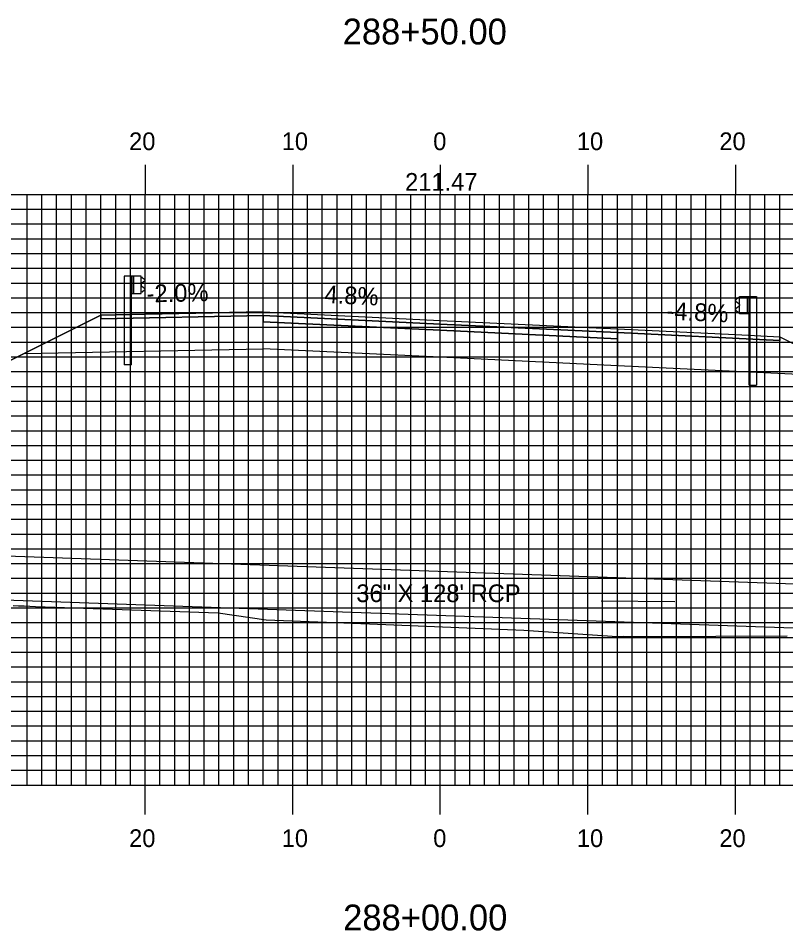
# Model space of a CAD drawing. Extents: x 1812948 to 1813291, y 442591 to 442811.
# Drawn here: x 1813084.9 to 1813136.9, y 442658.8 to 442720.6 of the extents above; entities that cross this region are included whole.
import ezdxf

# ---------------------------------------------------------------- set-up
doc = ezdxf.new("R2010")
doc.units = 0
for name, color, linetype in [('ANNOTATION', 7, 'Continuous'), ('D_Drainage_Culvert', 7, 'Continuous'), ('D_Drainage_Text', 7, 'Continuous'), ('D_Guardrail_Beam_Lt', 7, 'Continuous'), ('D_Guardrail_Beam_Rt', 7, 'Continuous'), ('D_Roadway_Centerline', 7, 'Continuous'), ('D_Roadway_Centerline_Text', 7, 'Continuous'), ('D_Roadway_Edge_Shoulder', 7, 'Continuous'), ('D_Roadway_Edge_TW', 7, 'Continuous'), ('D_Roadway_Pavement', 7, 'Continuous'), ('D_Roadway_SlopeLines', 7, 'Continuous'), ('D_Roadway_SubGrade', 7, 'Continuous'), ('Default', 7, 'Continuous'), ('H_V ANNOTATION', 7, 'Continuous'), ('MAJOR', 7, 'Continuous'), ('MINOR', 7, 'Continuous'), ('S_Roadway_Centerline', 7, 'Continuous')]:
    doc.layers.add(name, color=color, linetype=linetype)

msp = doc.modelspace()

# ---------------------------------------------------------------- linework, layer by layer
at = {"layer": 'D_Drainage_Culvert'}
msp.add_line((1813124.351, 442681.144), (1813129.339, 442681.103), dxfattribs=at)
msp.add_lwpolyline([(1813053.993, 442682.258), (1813054.1, 442685.256), (1813182.019, 442680.701), (1813181.912, 442677.703)], close=True, dxfattribs=at)
at = {"layer": 'D_Guardrail_Beam_Lt'}
for p, q in [((1813092.026, 442703.132), (1813092.026, 442697.132)), ((1813092.497, 442703.132), (1813092.026, 442703.132)), ((1813093.184, 442703.132), (1813092.497, 442703.132)), ((1813092.497, 442703.132), (1813092.497, 442701.965)), ((1813092.559, 442703.132), (1813092.559, 442701.965)), ((1813092.663, 442703.132), (1813092.663, 442701.965)), ((1813093.184, 442701.965), (1813093.184, 442703.132)), ((1813093.184, 442703.049), (1813093.258, 442703.034)), ((1813093.189, 442702.584), (1813093.189, 442702.514)), ((1813093.418, 442702.784), (1813093.222, 442702.648)), ((1813093.274, 442703.027), (1813093.418, 442702.927)), ((1813092.497, 442701.965), (1813093.184, 442701.965)), ((1813092.518, 442697.132), (1813092.518, 442701.965)), ((1813093.258, 442702.063), (1813093.184, 442702.049)), ((1813093.222, 442702.449), (1813093.418, 442702.313)), ((1813093.418, 442702.17), (1813093.274, 442702.07)), ((1813092.518, 442697.132), (1813092.026, 442697.132))]:
    msp.add_line(p, q, dxfattribs=at)
for centre, major_axis, start_param, end_param in [((1813093.268, 442702.584), (-0.0789, 0), 5.323254, 6.283185), ((1813093.25, 442702.993), (0.0417, 0), 0.959931, 1.376053), ((1813093.367, 442702.856), (0.0877, 0), 5.323254, 7.243116), ((1813093.268, 442702.514), (-0.0789, 0), 6.283185, 7.243116), ((1813093.25, 442702.104), (0.0417, 0), 4.907132, 5.323254), ((1813093.367, 442702.242), (0.0877, 0), 5.323254, 7.243116)]:
    msp.add_ellipse(centre, major_axis=major_axis, ratio=0.995501, start_param=start_param, end_param=end_param, dxfattribs=at)
at = {"layer": 'D_Guardrail_Beam_Rt'}
for p, q in [((1813133.636, 442701.651), (1813133.493, 442701.551)), ((1813133.493, 442701.408), (1813133.688, 442701.272)), ((1813133.726, 442701.673), (1813133.652, 442701.658)), ((1813133.726, 442701.756), (1813134.413, 442701.756)), ((1813133.726, 442700.589), (1813133.726, 442701.756)), ((1813134.247, 442701.756), (1813134.247, 442700.589)), ((1813134.351, 442701.756), (1813134.351, 442700.589)), ((1813134.413, 442701.756), (1813134.884, 442701.756)), ((1813134.413, 442701.756), (1813134.413, 442700.589)), ((1813134.884, 442701.756), (1813134.884, 442695.756)), ((1813133.688, 442701.073), (1813133.493, 442700.937)), ((1813133.493, 442700.794), (1813133.636, 442700.694)), ((1813133.722, 442701.208), (1813133.722, 442701.138)), ((1813133.652, 442700.687), (1813133.726, 442700.673)), ((1813134.413, 442700.589), (1813133.726, 442700.589)), ((1813134.393, 442695.756), (1813134.393, 442700.589)), ((1813134.393, 442695.756), (1813134.884, 442695.756))]:
    msp.add_line(p, q, dxfattribs=at)
for centre, major_axis, start_param, end_param in [((1813133.543, 442701.48), (-0.0877, 0), 5.323254, 7.243116), ((1813133.66, 442701.617), (-0.0417, 0), 4.907132, 5.323254), ((1813133.543, 442700.866), (-0.0877, 0), 5.323254, 7.243116), ((1813133.643, 442701.208), (0.0789, 0), 0, 0.959931), ((1813133.643, 442701.138), (0.0789, 0), 5.323254, 6.283185), ((1813133.66, 442700.728), (-0.0417, 0), 0.959931, 1.376053)]:
    msp.add_ellipse(centre, major_axis=major_axis, ratio=0.995501, start_param=start_param, end_param=end_param, dxfattribs=at)
at = {"layer": 'D_Roadway_Centerline'}
msp.add_lwpolyline([(1813053.993, 442682.258), (1813085.247, 442697.885), (1813090.455, 442700.489), (1813093.455, 442700.549), (1813101.455, 442700.709), (1813113.455, 442700.133), (1813125.455, 442699.557), (1813133.455, 442699.173), (1813136.455, 442699.029), (1813141.986, 442696.263), (1813179.261, 442677.626)], dxfattribs=at)
at = {"layer": 'D_Roadway_Edge_Shoulder'}
for points in [[(1813101.455, 442700.709), (1813093.455, 442700.549), (1813093.455, 442700.549), (1813090.455, 442700.489), (1813090.455, 442700.239), (1813101.455, 442700.459)], [(1813125.455, 442699.557), (1813133.455, 442699.173), (1813133.455, 442699.173), (1813136.455, 442699.029), (1813136.455, 442698.779), (1813125.455, 442699.307)]]:
    msp.add_lwpolyline(points, close=True, dxfattribs=at)
at = {"layer": 'D_Roadway_Edge_TW'}
msp.add_lwpolyline([(1813101.455, 442700.459), (1813101.455, 442700.709), (1813113.455, 442700.133), (1813125.455, 442699.557), (1813125.455, 442699.307), (1813113.455, 442699.883)], close=True, dxfattribs=at)
at = {"layer": 'D_Roadway_Pavement'}
msp.add_lwpolyline([(1813101.455, 442700.042), (1813101.455, 442700.459), (1813113.455, 442699.883), (1813125.455, 442699.307), (1813125.455, 442698.89), (1813113.455, 442699.466)], close=True, dxfattribs=at)
for points in [[(1813101.455, 442700.459), (1813101.455, 442700.042)], [(1813125.455, 442699.307), (1813125.455, 442698.89)]]:
    msp.add_lwpolyline(points, dxfattribs=at)
at = {"layer": 'D_Roadway_SlopeLines'}
for points in [[(1813090.455, 442700.489), (1813053.993, 442682.258)], [(1813136.455, 442699.029), (1813179.261, 442677.626)]]:
    msp.add_lwpolyline(points, dxfattribs=at)
at = {"layer": 'D_Roadway_SubGrade'}
for points in [[(1813101.455, 442700.042), (1813101.455, 442700.459), (1813090.455, 442700.239), (1813090.455, 442700.489), (1813085.247, 442697.885), (1813101.455, 442698.209)], [(1813101.455, 442698.209), (1813101.455, 442700.459), (1813101.455, 442700.042), (1813113.455, 442699.466), (1813125.455, 442698.89), (1813125.455, 442699.307), (1813125.455, 442697.057), (1813113.455, 442697.633)], [(1813125.455, 442698.89), (1813125.455, 442699.307), (1813136.455, 442698.779), (1813136.455, 442699.029), (1813141.986, 442696.263), (1813125.455, 442697.057)]]:
    msp.add_lwpolyline(points, close=True, dxfattribs=at)
at = {"layer": 'Default'}
msp.add_lwpolyline([(1813053.993, 442682.258), (1813054.1, 442685.256), (1813182.019, 442680.701), (1813181.912, 442677.703)], close=True, dxfattribs=at)
at = {"layer": 'MAJOR'}
for p, q in [((1813093.455, 442710.669), (1813093.455, 442708.665)), ((1813103.455, 442710.669), (1813103.455, 442708.665)), ((1813113.455, 442710.669), (1813113.455, 442708.665)), ((1813123.455, 442710.669), (1813123.455, 442708.665)), ((1813133.455, 442710.669), (1813133.455, 442708.665)), ((1812973.455, 442708.665), (1813253.455, 442708.665)), ((1812973.455, 442708.665), (1813253.455, 442708.665)), ((1813093.455, 442668.665), (1813093.455, 442708.665)), ((1813103.455, 442668.665), (1813103.455, 442708.665)), ((1813113.455, 442668.665), (1813113.455, 442708.665)), ((1813123.455, 442668.665), (1813123.455, 442708.665)), ((1813133.455, 442668.665), (1813133.455, 442708.665)), ((1812973.455, 442703.665), (1813253.455, 442703.665)), ((1812973.455, 442698.665), (1813253.455, 442698.665)), ((1812973.455, 442693.665), (1813253.455, 442693.665)), ((1812973.455, 442688.665), (1813253.455, 442688.665)), ((1812973.455, 442683.665), (1813253.455, 442683.665)), ((1812973.455, 442678.665), (1813253.455, 442678.665)), ((1812973.455, 442673.665), (1813253.455, 442673.665)), ((1812973.455, 442668.665), (1813253.455, 442668.665)), ((1812973.455, 442668.665), (1813253.455, 442668.665)), ((1813093.455, 442666.661), (1813093.455, 442668.665)), ((1813103.455, 442666.661), (1813103.455, 442668.665)), ((1813113.455, 442666.661), (1813113.455, 442668.665)), ((1813123.455, 442666.661), (1813123.455, 442668.665)), ((1813133.455, 442666.661), (1813133.455, 442668.665))]:
    msp.add_line(p, q, dxfattribs=at)
at = {"layer": 'MINOR'}
for p, q in [((1813085.455, 442668.665), (1813085.455, 442708.665)), ((1813086.455, 442668.665), (1813086.455, 442708.665)), ((1813087.455, 442668.665), (1813087.455, 442708.665)), ((1813088.455, 442668.665), (1813088.455, 442708.665)), ((1813089.455, 442668.665), (1813089.455, 442708.665)), ((1813090.455, 442668.665), (1813090.455, 442708.665)), ((1813091.455, 442668.665), (1813091.455, 442708.665)), ((1813092.455, 442668.665), (1813092.455, 442708.665)), ((1813094.455, 442668.665), (1813094.455, 442708.665)), ((1813095.455, 442668.665), (1813095.455, 442708.665)), ((1813096.455, 442668.665), (1813096.455, 442708.665)), ((1813097.455, 442668.665), (1813097.455, 442708.665)), ((1813098.455, 442668.665), (1813098.455, 442708.665)), ((1813099.455, 442668.665), (1813099.455, 442708.665)), ((1813100.455, 442668.665), (1813100.455, 442708.665)), ((1813101.455, 442668.665), (1813101.455, 442708.665)), ((1813102.455, 442668.665), (1813102.455, 442708.665)), ((1813104.455, 442668.665), (1813104.455, 442708.665)), ((1813105.455, 442668.665), (1813105.455, 442708.665)), ((1813106.455, 442668.665), (1813106.455, 442708.665)), ((1813107.455, 442668.665), (1813107.455, 442708.665)), ((1813108.455, 442668.665), (1813108.455, 442708.665)), ((1813109.455, 442668.665), (1813109.455, 442708.665)), ((1813110.455, 442668.665), (1813110.455, 442708.665)), ((1813111.455, 442668.665), (1813111.455, 442708.665)), ((1813112.455, 442668.665), (1813112.455, 442708.665)), ((1813114.455, 442668.665), (1813114.455, 442708.665)), ((1813115.455, 442668.665), (1813115.455, 442708.665)), ((1813116.455, 442668.665), (1813116.455, 442708.665)), ((1813117.455, 442668.665), (1813117.455, 442708.665)), ((1813118.455, 442668.665), (1813118.455, 442708.665)), ((1813119.455, 442668.665), (1813119.455, 442708.665)), ((1813120.455, 442668.665), (1813120.455, 442708.665)), ((1813121.455, 442668.665), (1813121.455, 442708.665)), ((1813122.455, 442668.665), (1813122.455, 442708.665)), ((1813124.455, 442668.665), (1813124.455, 442708.665)), ((1813125.455, 442668.665), (1813125.455, 442708.665)), ((1813126.455, 442668.665), (1813126.455, 442708.665)), ((1813127.455, 442668.665), (1813127.455, 442708.665)), ((1813128.455, 442668.665), (1813128.455, 442708.665)), ((1813129.455, 442668.665), (1813129.455, 442708.665)), ((1813130.455, 442668.665), (1813130.455, 442708.665)), ((1813131.455, 442668.665), (1813131.455, 442708.665)), ((1813132.455, 442668.665), (1813132.455, 442708.665)), ((1813134.455, 442668.665), (1813134.455, 442708.665)), ((1813135.455, 442668.665), (1813135.455, 442708.665)), ((1813136.455, 442668.665), (1813136.455, 442708.665)), ((1812973.455, 442707.665), (1813253.455, 442707.665)), ((1812973.455, 442706.665), (1813253.455, 442706.665)), ((1812973.455, 442705.665), (1813253.455, 442705.665)), ((1812973.455, 442704.665), (1813253.455, 442704.665)), ((1812973.455, 442702.665), (1813253.455, 442702.665)), ((1812973.455, 442701.665), (1813253.455, 442701.665)), ((1812973.455, 442700.665), (1813253.455, 442700.665)), ((1812973.455, 442699.665), (1813253.455, 442699.665)), ((1812973.455, 442697.665), (1813253.455, 442697.665)), ((1812973.455, 442696.665), (1813253.455, 442696.665)), ((1812973.455, 442695.665), (1813253.455, 442695.665)), ((1812973.455, 442694.665), (1813253.455, 442694.665)), ((1812973.455, 442692.665), (1813253.455, 442692.665)), ((1812973.455, 442691.665), (1813253.455, 442691.665)), ((1812973.455, 442690.665), (1813253.455, 442690.665)), ((1812973.455, 442689.665), (1813253.455, 442689.665)), ((1812973.455, 442687.665), (1813253.455, 442687.665)), ((1812973.455, 442686.665), (1813253.455, 442686.665)), ((1812973.455, 442685.665), (1813253.455, 442685.665)), ((1812973.455, 442684.665), (1813253.455, 442684.665)), ((1812973.455, 442682.665), (1813253.455, 442682.665)), ((1812973.455, 442681.665), (1813253.455, 442681.665)), ((1812973.455, 442680.665), (1813253.455, 442680.665)), ((1812973.455, 442679.665), (1813253.455, 442679.665)), ((1812973.455, 442677.665), (1813253.455, 442677.665)), ((1812973.455, 442676.665), (1813253.455, 442676.665)), ((1812973.455, 442675.665), (1813253.455, 442675.665)), ((1812973.455, 442674.665), (1813253.455, 442674.665)), ((1812973.455, 442672.665), (1813253.455, 442672.665)), ((1812973.455, 442671.665), (1813253.455, 442671.665)), ((1812973.455, 442670.665), (1813253.455, 442670.665)), ((1812973.455, 442669.665), (1813253.455, 442669.665))]:
    msp.add_line(p, q, dxfattribs=at)
at = {"layer": 'S_Roadway_Centerline'}
msp.add_lwpolyline([(1813084.51, 442680.82), (1813084.87, 442680.808), (1813085.247, 442680.795), (1813085.633, 442680.781), (1813086.022, 442680.767), (1813098.399, 442680.331), (1813101.644, 442679.853), (1813108.653, 442679.577), (1813119.109, 442679.156), (1813125.45, 442678.736), (1813125.876, 442678.737), (1813126.291, 442678.735), (1813126.755, 442678.73), (1813127.287, 442678.726), (1813136.95, 442678.762)], dxfattribs=at)

# ---------------------------------------------------------------- texts
at = {"layer": 'ANNOTATION'}
for s, rotation, p in [('-2.0%', 1.14576, (1813093.561, 442701.351)), ('4.8%', 357.25191, (1813105.584, 442701.313)), ('-4.8%', 357.25191, (1813128.764, 442700.2))]:
    msp.add_text(s, height=1.2, rotation=rotation, dxfattribs=at).set_placement(p)
at = {"layer": 'D_Drainage_Text'}
msp.add_text('36" X 128\' RCP', height=1.2, dxfattribs=at).set_placement((1813107.76, 442681.054))
at = {"layer": 'D_Roadway_Centerline'}
for s, p in [('C', (1813113.45, 442700.133)), ('L', (1813113.455, 442700.125))]:
    msp.add_text(s, height=0.0146, dxfattribs=at).set_placement(p)
at = {"layer": 'D_Roadway_Centerline_Text'}
msp.add_text('211.47', height=1.2, dxfattribs=at).set_placement((1813111.069, 442708.913))
at = {"layer": 'H_V ANNOTATION'}
for s, height, p in [('288+50.00', 1.75, (1813106.838, 442718.821)), ('20', 1.2, (1813092.363, 442711.665)), ('10', 1.2, (1813102.706, 442711.665)), ('0', 1.2, (1813112.973, 442711.665)), ('10', 1.2, (1813122.706, 442711.665)), ('20', 1.2, (1813132.363, 442711.665)), ('20', 1.2, (1813092.363, 442664.465)), ('10', 1.2, (1813102.706, 442664.465)), ('0', 1.2, (1813112.973, 442664.465)), ('10', 1.2, (1813122.706, 442664.465)), ('20', 1.2, (1813132.363, 442664.465)), ('288+00.00', 1.75, (1813106.869, 442658.821))]:
    msp.add_text(s, height=height, dxfattribs=at).set_placement(p)

doc.saveas('drawing.dxf')
